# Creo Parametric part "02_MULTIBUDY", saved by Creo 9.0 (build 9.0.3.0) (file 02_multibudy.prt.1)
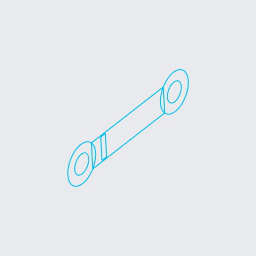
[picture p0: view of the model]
Units: millimeter Kilogram Sec (mmKs); MM, KILOGRAM, SECS
Materials in the file: S235JRG2

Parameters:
  BENENNUNG = "XXX"
  DATUM = "XX.XX.XX"
  ERSTELLER = "ARINDA"
  TEILETYP = "Fertigungsteil"
  PTC_MASTER_MATERIAL = "S235JRG2"
  SELECT_EN_NAME = "S235JRG2"
  SELECT_DIN_NAME = "RSt37-2"
  SELECT_DIN_NUMBER = "1.0038"
  SELECT_ASTM_NAME = "A 283 M Grade 2"
  MATERIAL_GROUP = "ME_ST_Baustahl"
  STANDARD_EN_DELIVERYSPEC = "DIN EN 10025"
  STANDARD_DIN_DELIVERYSPEC = "DIN 17100"

Other parameters: MASSE

Created from: ARINDA-STARTTEIL.PRT

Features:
  1. coordinate system "CS0"
  2. datum plane "DTM1", "T_RECHTS_Y-Z"
  3. datum plane "DTM2", "T_OBEN_X-Z"
  4. datum plane "DTM3", "T_VORNE_X-Y"
  5. datum axis "T_X-ACHSE"
  6. datum axis "A_1"
  7. datum axis "A_2"
  8. datum plane "DTM1", "P_SPIEGEL_1"
  9. datum plane "DTM2", "P_SPIEGEL_2"
  10. sketch "Skizze 1"

Other named items: T_BASIC, T_Y-ACHSE, T_Z-ACHSE

Layers: 00_STD-ACHSEN, 00_STD-EBENEN, 00_STD-KOORDSYS, 01_EBENEN, 01_KURVEN, KURVENELEMENTE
